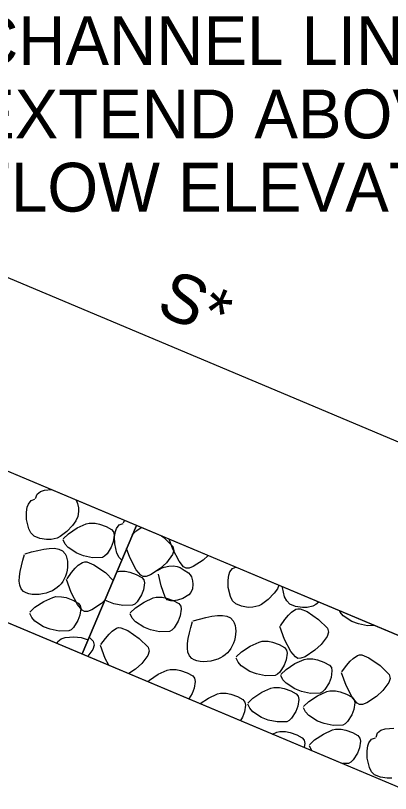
# Model space of a CAD drawing. Extents: x 3 to 3592, y -602 to 1171.
# Drawn here: x 111.1 to 137.9, y 901.7 to 957.5 of the extents above; entities that cross this region are included whole.
import ezdxf

# ---------------------------------------------------------------- set-up
doc = ezdxf.new("R2010")
doc.units = 0
doc.layers.add('2', color=7, linetype='Continuous')
doc.layers.add('3', color=7, linetype='Continuous')

msp = doc.modelspace()

# ---------------------------------------------------------------- linework, layer by layer
at = {"layer": '2'}
for p, q in [((131.449, 929.873), (100.911, 942.731)), ((146.55, 923.515), (131.449, 929.873)), ((115.824, 911.743), (119.705, 920.959))]:
    msp.add_line(p, q, dxfattribs=at)
for points in [[(78.674, 938.235), (141.594, 911.743), (187.555, 911.743), (250.474, 938.235)], [(112.595, 923.2), (112.837, 923.382)], [(112.837, 923.382), (113.131, 923.482)], [(113.131, 923.482), (113.622, 923.52)], [(112.168, 922.737), (112.444, 922.835)], [(112.485, 922.895), (112.595, 923.2)], [(115.4, 922.772), (115.494, 922.53)], [(111.837, 921.9), (111.895, 922.258)], [(111.895, 922.258), (111.977, 922.487)], [(111.977, 922.487), (112.168, 922.737)], [(115.494, 922.53), (115.551, 922.209)], [(115.551, 922.209), (115.56, 921.96)], [(92.074, 921.743), (139.574, 901.743), (189.574, 901.743), (237.074, 921.743)], [(111.848, 921.376), (111.837, 921.9)], [(115.56, 921.96), (115.51, 921.597)], [(112.003, 920.714), (111.848, 921.376)], [(115.373, 921.28), (115.136, 920.957)], [(115.51, 921.597), (115.373, 921.28)], [(116.118, 921.067), (116.331, 921.12)], [(116.331, 921.12), (116.747, 921.116)], [(116.747, 921.116), (117.072, 921.048)], [(118.793, 921.144), (118.855, 921.317)], [(112.157, 920.413), (112.003, 920.714)], [(115.136, 920.957), (114.717, 920.516)], [(114.838, 920.356), (115.467, 920.773)], [(115.467, 920.773), (116.118, 921.067)], [(117.072, 921.048), (117.542, 920.877)], [(117.542, 920.877), (117.936, 920.663)], [(117.936, 920.663), (118.076, 920.486)], [(118.203, 920.507), (118.286, 920.736)], [(118.286, 920.736), (118.476, 920.986)], [(118.476, 920.986), (118.753, 921.083)], [(119.528, 920.396), (119.733, 920.6)], [(119.733, 920.6), (120.044, 920.807)], [(120.044, 920.807), (120.057, 920.811)], [(112.384, 920.189), (112.157, 920.413)], [(112.794, 920.023), (112.384, 920.189)], [(113.282, 919.942), (112.794, 920.023)], [(114.034, 920.043), (113.616, 919.948)], [(114.242, 920.149), (114.034, 920.043)], [(114.717, 920.516), (114.242, 920.149)], [(114.462, 919.996), (114.838, 920.356)], [(118.119, 920.262), (118.05, 919.782)], [(118.076, 920.486), (118.119, 920.262)], [(118.146, 920.148), (118.203, 920.507)], [(118.156, 919.625), (118.146, 920.148)], [(119.404, 920.245), (119.528, 920.396)], [(121.494, 920.206), (121.679, 920.079)], [(121.679, 920.079), (122.311, 919.45)], [(113.616, 919.948), (113.282, 919.942)], [(114.608, 919.622), (114.462, 919.916)], [(114.832, 919.364), (114.608, 919.622)], [(118.05, 919.782), (117.906, 919.403)], [(118.311, 918.963), (118.156, 919.625)], [(122.314, 919.248), (122.044, 919.974)], [(122.311, 919.45), (122.385, 919.165)], [(115.449, 918.96), (114.832, 919.364)], [(115.928, 918.777), (115.449, 918.96)], [(117.604, 918.916), (117.435, 918.75)], [(117.906, 919.403), (117.604, 918.916)], [(118.465, 918.662), (118.311, 918.963)], [(119.241, 918.649), (119.002, 919.291)], [(122.289, 918.863), (121.861, 918.284)], [(122.385, 919.165), (122.289, 918.863)], [(122.767, 918.38), (122.314, 919.248)], [(115.85, 918.302), (116.005, 918.346)], [(116.568, 918.642), (115.928, 918.777)], [(116.005, 918.346), (116.158, 918.339)], [(116.158, 918.339), (116.669, 918.134)], [(117.269, 918.663), (116.568, 918.642)], [(117.435, 918.75), (117.269, 918.663)], [(118.657, 918.472), (118.465, 918.662)], [(119.694, 917.78), (119.241, 918.649)], [(123.087, 917.994), (122.767, 918.38)], [(124.485, 918.471), (123.781, 918.008)], [(124.84, 918.797), (124.485, 918.471)], [(115.07, 917.571), (115.334, 917.891)], [(115.334, 917.891), (115.539, 918.095)], [(115.539, 918.095), (115.85, 918.302)], [(116.669, 918.134), (117.486, 917.574)], [(120.014, 917.395), (119.694, 917.78)], [(121.411, 917.871), (120.708, 917.409)], [(121.206, 917.727), (121.485, 917.887)], [(121.861, 918.284), (121.411, 917.871)], [(121.485, 917.887), (121.702, 917.969)], [(121.702, 917.969), (122.032, 918.038)], [(122.032, 918.038), (122.357, 918.05)], [(122.357, 918.05), (122.634, 918.003)], [(122.634, 918.003), (122.838, 917.926)], [(122.838, 917.926), (123.136, 917.758)], [(123.263, 917.889), (123.087, 917.994)], [(123.136, 917.758), (123.427, 917.545)], [(123.484, 917.895), (123.263, 917.889)], [(123.781, 918.008), (123.484, 917.895)], [(126.409, 917.626), (126.6, 917.875)], [(126.6, 917.875), (126.833, 917.958)], [(114.744, 917.127), (115.07, 917.571)], [(117.486, 917.574), (118.045, 917.017)], [(118.307, 917.639), (118.491, 917.685)], [(118.491, 917.685), (118.906, 917.681)], [(118.906, 917.681), (119.232, 917.613)], [(119.232, 917.613), (119.701, 917.442)], [(119.701, 917.442), (120.095, 917.228)], [(120.19, 917.289), (120.014, 917.395)], [(120.095, 917.228), (120.235, 917.05)], [(120.41, 917.295), (120.19, 917.289)], [(120.708, 917.409), (120.41, 917.295)], [(121.485, 916.621), (121.287, 917.465)], [(123.427, 917.545), (123.56, 917.407)], [(123.56, 917.407), (123.647, 917.261)], [(123.647, 917.261), (123.736, 916.973)], [(126.269, 917.038), (126.326, 917.397)], [(126.326, 917.397), (126.409, 917.626)], [(115.047, 916.144), (114.704, 917.066)], [(120.278, 916.827), (120.209, 916.347)], [(120.235, 917.05), (120.278, 916.827)], [(123.755, 916.744), (123.717, 916.418)], [(123.736, 916.973), (123.755, 916.744)], [(126.28, 916.515), (126.269, 917.038)], [(129.909, 916.662), (129.804, 916.418)], [(115.5, 915.275), (115.047, 916.144)], [(120.209, 916.347), (120.066, 915.968)], [(121.771, 915.809), (121.485, 916.621)], [(123.609, 916.152), (123.458, 915.984)], [(123.717, 916.418), (123.609, 916.152)], [(126.435, 915.852), (126.28, 916.515)], [(129.567, 916.095), (129.149, 915.654)], [(129.804, 916.418), (129.567, 916.095)], [(130.161, 916.508), (130.159, 916.557)], [(130.316, 915.845), (130.161, 916.508)], [(113.076, 915.503), (113.727, 915.796)], [(113.727, 915.796), (113.94, 915.85)], [(113.94, 915.85), (114.355, 915.845)], [(114.355, 915.845), (114.681, 915.778)], [(114.681, 915.778), (115.15, 915.607)], [(115.15, 915.607), (115.544, 915.392)], [(117.433, 915.564), (117.218, 915.366)], [(117.608, 915.525), (117.458, 915.623)], [(118.087, 915.342), (117.608, 915.525)], [(120.066, 915.968), (119.763, 915.48)], [(120.269, 915.463), (120.92, 915.757)], [(120.92, 915.757), (121.133, 915.81)], [(121.133, 915.81), (121.549, 915.806)], [(121.549, 915.806), (121.874, 915.738)], [(121.833, 915.704), (121.771, 915.809)], [(121.922, 915.628), (121.833, 915.704)], [(121.874, 915.738), (122.343, 915.567)], [(122.166, 915.549), (121.922, 915.628)], [(122.364, 915.546), (122.166, 915.549)], [(122.343, 915.567), (122.737, 915.353)], [(122.65, 915.592), (122.364, 915.546)], [(123.033, 915.724), (122.65, 915.592)], [(123.458, 915.984), (123.033, 915.724)], [(126.588, 915.551), (126.435, 915.852)], [(126.815, 915.327), (126.588, 915.551)], [(129.149, 915.654), (128.673, 915.287)], [(130.469, 915.544), (130.316, 915.845)], [(130.696, 915.32), (130.469, 915.544)], [(112.071, 914.726), (112.446, 915.086)], [(112.446, 915.086), (113.076, 915.503)], [(115.82, 914.89), (115.5, 915.275)], [(115.544, 915.392), (115.685, 915.215)], [(115.728, 914.992), (115.658, 914.512)], [(115.685, 915.215), (115.728, 914.992)], [(117.218, 915.366), (116.514, 914.904)], [(118.727, 915.207), (118.087, 915.342)], [(119.428, 915.228), (118.727, 915.207)], [(119.264, 914.686), (119.64, 915.046)], [(119.594, 915.315), (119.428, 915.228)], [(119.763, 915.48), (119.594, 915.315)], [(119.64, 915.046), (120.269, 915.463)], [(122.737, 915.353), (122.878, 915.175)], [(122.878, 915.175), (122.921, 914.952)], [(127.226, 915.161), (126.815, 915.327)], [(127.713, 915.081), (127.226, 915.161)], [(128.048, 915.086), (127.713, 915.081)], [(128.466, 915.182), (128.048, 915.086)], [(128.673, 915.287), (128.466, 915.182)], [(131.107, 915.154), (130.696, 915.32)], [(131.594, 915.073), (131.107, 915.154)], [(131.119, 914.941), (131.274, 914.984)], [(131.274, 914.984), (131.426, 914.978)], [(131.426, 914.978), (131.937, 914.773)], [(131.929, 915.079), (131.594, 915.073)], [(132.347, 915.174), (131.929, 915.079)], [(132.554, 915.28), (132.347, 915.174)], [(132.78, 915.454), (132.554, 915.28)], [(112.216, 914.351), (112.071, 914.645)], [(115.658, 914.512), (115.515, 914.133)], [(115.997, 914.784), (115.82, 914.89)], [(116.217, 914.79), (115.997, 914.784)], [(116.514, 914.904), (116.217, 914.79)], [(119.41, 914.311), (119.264, 914.606)], [(122.852, 914.472), (122.708, 914.093)], [(122.921, 914.952), (122.852, 914.472)], [(130.338, 914.21), (130.603, 914.529)], [(130.603, 914.529), (130.808, 914.734)], [(130.808, 914.734), (131.119, 914.941)], [(131.937, 914.773), (132.754, 914.213)], [(134.29, 914.74), (134.241, 914.839)], [(134.515, 914.482), (134.29, 914.74)], [(135.131, 914.078), (134.515, 914.482)], [(112.441, 914.093), (112.216, 914.351)], [(113.057, 913.69), (112.441, 914.093)], [(115.515, 914.133), (115.212, 913.645)], [(119.634, 914.054), (119.41, 914.311)], [(120.251, 913.65), (119.634, 914.054)], [(122.708, 914.093), (122.405, 913.605)], [(130.013, 913.766), (130.338, 914.21)], [(132.754, 914.213), (133.385, 913.584)], [(135.61, 913.895), (135.131, 914.078)], [(136.251, 913.76), (135.61, 913.895)], [(113.536, 913.507), (113.057, 913.69)], [(114.177, 913.372), (113.536, 913.507)], [(114.878, 913.393), (114.177, 913.372)], [(115.044, 913.48), (114.878, 913.393)], [(115.212, 913.645), (115.044, 913.48)], [(117.759, 913.171), (117.964, 913.375)], [(117.964, 913.375), (118.275, 913.583)], [(118.275, 913.583), (118.43, 913.626)], [(118.43, 913.626), (118.583, 913.619)], [(118.583, 913.619), (119.094, 913.414)], [(119.094, 913.414), (119.911, 912.854)], [(120.729, 913.467), (120.251, 913.65)], [(121.37, 913.332), (120.729, 913.467)], [(122.071, 913.353), (121.37, 913.332)], [(122.237, 913.44), (122.071, 913.353)], [(122.405, 913.605), (122.237, 913.44)], [(130.315, 912.782), (129.972, 913.705)], [(133.459, 913.299), (133.363, 912.997)], [(133.385, 913.584), (133.459, 913.299)], [(136.766, 913.776), (136.251, 913.76)], [(114.075, 912.64), (114.317, 912.822)], [(114.317, 912.822), (114.612, 912.922)], [(114.612, 912.922), (115.24, 912.971)], [(115.24, 912.971), (115.742, 912.914)], [(115.742, 912.914), (116.247, 912.748)], [(116.33, 912.944), (116.621, 912.654)], [(117.169, 912.408), (117.495, 912.851)], [(117.495, 912.851), (117.759, 913.171)], [(119.911, 912.854), (120.542, 912.226)], [(130.769, 911.914), (130.315, 912.782)], [(133.363, 912.997), (132.935, 912.418)], [(114.025, 912.501), (114.075, 912.64)], [(116.695, 912.369), (116.599, 912.067)], [(116.621, 912.654), (116.695, 912.369)], [(117.472, 911.424), (117.129, 912.347)], [(120.542, 912.226), (120.616, 911.941)], [(127.223, 911.886), (127.852, 912.303)], [(127.852, 912.303), (128.503, 912.597)], [(128.503, 912.597), (128.716, 912.65)], [(128.716, 912.65), (129.132, 912.646)], [(129.132, 912.646), (129.457, 912.578)], [(129.457, 912.578), (129.926, 912.407)], [(129.926, 912.407), (130.321, 912.193)], [(130.321, 912.193), (130.461, 912.016)], [(132.935, 912.418), (132.486, 912.005)], [(116.599, 912.067), (116.233, 911.571)], [(120.52, 911.638), (120.092, 911.06)], [(120.616, 911.941), (120.52, 911.638)], [(126.847, 911.527), (127.223, 911.886)], [(130.504, 911.792), (130.435, 911.312)], [(130.461, 912.016), (130.504, 911.792)], [(131.088, 911.528), (130.769, 911.914)], [(132.486, 912.005), (131.783, 911.542)], [(135.222, 911.427), (135.533, 911.634)], [(135.533, 911.634), (135.688, 911.677)], [(135.688, 911.677), (135.84, 911.671)], [(135.84, 911.671), (136.351, 911.466)], [(117.723, 910.944), (117.472, 911.424)], [(120.092, 911.06), (119.643, 910.647)], [(126.993, 911.152), (126.847, 911.446)], [(127.217, 910.894), (126.993, 911.152)], [(130.435, 911.312), (130.291, 910.933)], [(131.061, 911.049), (131.711, 911.343)], [(131.265, 911.423), (131.088, 911.528)], [(131.485, 911.429), (131.265, 911.423)], [(131.783, 911.542), (131.485, 911.429)], [(131.711, 911.343), (131.925, 911.396)], [(131.925, 911.396), (132.34, 911.392)], [(132.34, 911.392), (132.666, 911.324)], [(132.666, 911.324), (133.135, 911.153)], [(133.135, 911.153), (133.529, 910.939)], [(134.752, 910.903), (135.017, 911.223)], [(135.017, 911.223), (135.222, 911.427)], [(136.351, 911.466), (137.168, 910.906)], [(119.643, 910.647), (119.169, 910.335)], [(121.27, 910.282), (121.92, 910.575)], [(121.92, 910.575), (122.134, 910.628)], [(122.134, 910.628), (122.549, 910.624)], [(122.549, 910.624), (122.875, 910.557)], [(122.875, 910.557), (123.344, 910.385)], [(127.834, 910.491), (127.217, 910.894)], [(130.291, 910.933), (129.988, 910.446)], [(130.055, 910.272), (130.431, 910.632)], [(130.431, 910.632), (131.061, 911.049)], [(133.529, 910.939), (133.669, 910.762)], [(133.712, 910.538), (133.643, 910.058)], [(133.669, 910.762), (133.712, 910.538)], [(134.427, 910.459), (134.752, 910.903)], [(137.168, 910.906), (137.799, 910.277)], [(120.64, 909.865), (121.27, 910.282)], [(123.344, 910.385), (123.738, 910.171)], [(123.738, 910.171), (123.879, 909.994)], [(123.879, 909.994), (123.922, 909.77)], [(128.313, 910.307), (127.834, 910.491)], [(128.953, 910.172), (128.313, 910.307)], [(129.654, 910.194), (128.953, 910.172)], [(129.82, 910.281), (129.654, 910.194)], [(129.988, 910.446), (129.82, 910.281)], [(130.201, 909.898), (130.055, 910.192)], [(133.643, 910.058), (133.5, 909.679)], [(134.729, 909.476), (134.386, 910.398)], [(137.873, 909.992), (137.777, 909.69)], [(137.799, 910.277), (137.873, 909.992)], [(120.532, 909.761), (120.64, 909.865)], [(123.922, 909.77), (123.852, 909.29)], [(130.426, 909.64), (130.201, 909.898)], [(131.042, 909.236), (130.426, 909.64)], [(133.5, 909.679), (133.197, 909.192)], [(135.183, 908.607), (134.729, 909.476)], [(137.777, 909.69), (137.349, 909.111)], [(123.709, 908.911), (123.469, 908.525)], [(123.852, 909.29), (123.709, 908.911)], [(124.86, 908.584), (125.511, 908.877)], [(125.511, 908.877), (125.724, 908.931)], [(125.724, 908.931), (126.14, 908.926)], [(126.14, 908.926), (126.465, 908.859)], [(126.465, 908.859), (126.935, 908.688)], [(128.054, 908.58), (128.684, 908.997)], [(128.684, 908.997), (129.334, 909.291)], [(129.334, 909.291), (129.548, 909.344)], [(129.548, 909.344), (129.963, 909.34)], [(129.963, 909.34), (130.289, 909.272)], [(130.289, 909.272), (130.758, 909.101)], [(130.758, 909.101), (131.152, 908.887)], [(131.521, 909.053), (131.042, 909.236)], [(131.152, 908.887), (131.292, 908.71)], [(132.161, 908.918), (131.521, 909.053)], [(132.863, 908.939), (132.161, 908.918)], [(132.684, 908.746), (133.335, 909.04)], [(133.028, 909.026), (132.863, 908.939)], [(133.197, 909.192), (133.028, 909.026)], [(133.335, 909.04), (133.548, 909.093)], [(133.548, 909.093), (133.964, 909.089)], [(133.964, 909.089), (134.289, 909.021)], [(134.289, 909.021), (134.759, 908.85)], [(134.759, 908.85), (135.153, 908.636)], [(137.349, 909.111), (136.9, 908.698)], [(124.265, 908.189), (124.86, 908.584)], [(126.935, 908.688), (127.329, 908.473)], [(127.329, 908.473), (127.469, 908.296)], [(127.469, 908.296), (127.512, 908.073)], [(127.678, 908.22), (128.054, 908.58)], [(131.335, 908.486), (131.266, 908.006)], [(131.292, 908.71), (131.335, 908.486)], [(131.679, 907.969), (132.055, 908.329)], [(132.055, 908.329), (132.684, 908.746)], [(135.153, 908.636), (135.293, 908.459)], [(135.502, 908.222), (135.183, 908.607)], [(135.293, 908.459), (135.336, 908.235)], [(136.9, 908.698), (136.197, 908.236)], [(127.512, 908.073), (127.443, 907.593)], [(127.824, 907.846), (127.678, 908.14)], [(128.049, 907.588), (127.824, 907.846)], [(131.266, 908.006), (131.123, 907.627)], [(131.825, 907.595), (131.679, 907.889)], [(135.267, 907.755), (135.123, 907.376)], [(135.336, 908.235), (135.267, 907.755)], [(135.679, 908.116), (135.502, 908.222)], [(135.899, 908.122), (135.679, 908.116)], [(136.197, 908.236), (135.899, 908.122)], [(127.299, 907.214), (127.151, 906.974)], [(127.443, 907.593), (127.299, 907.214)], [(128.665, 907.184), (128.049, 907.588)], [(129.144, 907.001), (128.665, 907.184)], [(131.123, 907.627), (130.82, 907.14)], [(132.049, 907.337), (131.825, 907.595)], [(132.666, 906.933), (132.049, 907.337)], [(135.123, 907.376), (134.821, 906.889)], [(129.784, 906.866), (129.144, 907.001)], [(130.486, 906.887), (129.784, 906.866)], [(130.651, 906.974), (130.486, 906.887)], [(130.82, 907.14), (130.651, 906.974)], [(133.145, 906.75), (132.666, 906.933)], [(133.785, 906.615), (133.145, 906.75)], [(134.486, 906.636), (133.785, 906.615)], [(134.652, 906.723), (134.486, 906.636)], [(134.821, 906.889), (134.652, 906.723)], [(129.464, 906), (129.763, 906.134)], [(129.763, 906.134), (129.976, 906.188)], [(129.976, 906.188), (130.391, 906.183)], [(130.391, 906.183), (130.717, 906.116)], [(130.717, 906.116), (131.186, 905.945)], [(133.098, 906.003), (133.749, 906.297)], [(133.749, 906.297), (133.962, 906.35)], [(133.962, 906.35), (134.377, 906.346)], [(134.377, 906.346), (134.703, 906.278)], [(134.703, 906.278), (135.172, 906.107)], [(135.172, 906.107), (135.566, 905.893)], [(136.866, 905.783), (136.976, 906.088)], [(136.976, 906.088), (137.218, 906.271)], [(137.218, 906.271), (137.513, 906.37)], [(137.513, 906.37), (138.141, 906.42)], [(131.186, 905.945), (131.58, 905.73)], [(131.58, 905.73), (131.721, 905.553)], [(131.721, 905.553), (131.764, 905.33)], [(132.093, 905.226), (132.468, 905.586)], [(132.468, 905.586), (133.098, 906.003)], [(135.566, 905.893), (135.707, 905.716)], [(135.75, 905.492), (135.68, 905.012)], [(135.707, 905.716), (135.75, 905.492)], [(136.359, 905.376), (136.55, 905.625)], [(136.55, 905.625), (136.826, 905.723)], [(131.764, 905.33), (131.723, 905.049)], [(132.238, 904.852), (132.093, 905.146)], [(135.68, 905.012), (135.537, 904.633)], [(136.219, 904.788), (136.276, 905.147)], [(136.276, 905.147), (136.359, 905.376)], [(132.265, 904.821), (132.238, 904.852)], [(135.537, 904.633), (135.234, 904.146)], [(136.23, 904.265), (136.219, 904.788)], [(134.9, 903.893), (134.496, 903.881)], [(135.066, 903.98), (134.9, 903.893)], [(135.234, 904.146), (135.066, 903.98)], [(136.385, 903.602), (136.23, 904.265)], [(136.538, 903.301), (136.385, 903.602)], [(136.765, 903.077), (136.538, 903.301)], [(137.176, 902.911), (136.765, 903.077)], [(137.663, 902.831), (137.176, 902.911)], [(137.998, 902.836), (137.663, 902.831)]]:
    msp.add_lwpolyline(points, dxfattribs=at)
for points in [[(119.705, 920.959), (95.955, 930.959), (92.074, 921.743), (115.824, 911.743)], [(141.594, 911.743), (119.705, 920.959), (115.824, 911.743), (139.574, 901.743)]]:
    msp.add_lwpolyline(points, close=True, dxfattribs=at)
for points in [[(111.737, 918.929), (114.604, 918.929), (114.625, 917.314), (113.494, 916.183), (111.636, 916.223), (111.696, 918.869)], [(123.772, 914.121), (126.639, 914.121), (126.66, 912.506), (125.529, 911.375), (123.671, 911.415), (123.731, 914.061)]]:
    msp.add_spline(points, degree=3, dxfattribs=at)

# ---------------------------------------------------------------- texts
at = {"layer": '3'}
for s, p in [('CHANNEL LINING ELEVATION,', (107.87, 953.947)), ('EXTEND ABOVE THE DESIGN', (107.87, 948.697)), ('FLOW ELEVATION, AS REQUIRED.', (107.87, 943.447))]:
    msp.add_text(s, height=3.5, dxfattribs=at).set_placement(p)
msp.add_text('S*', height=3.5, rotation=337.1663, dxfattribs=at).set_placement((121.001, 936.171))

doc.saveas('drawing.dxf')
